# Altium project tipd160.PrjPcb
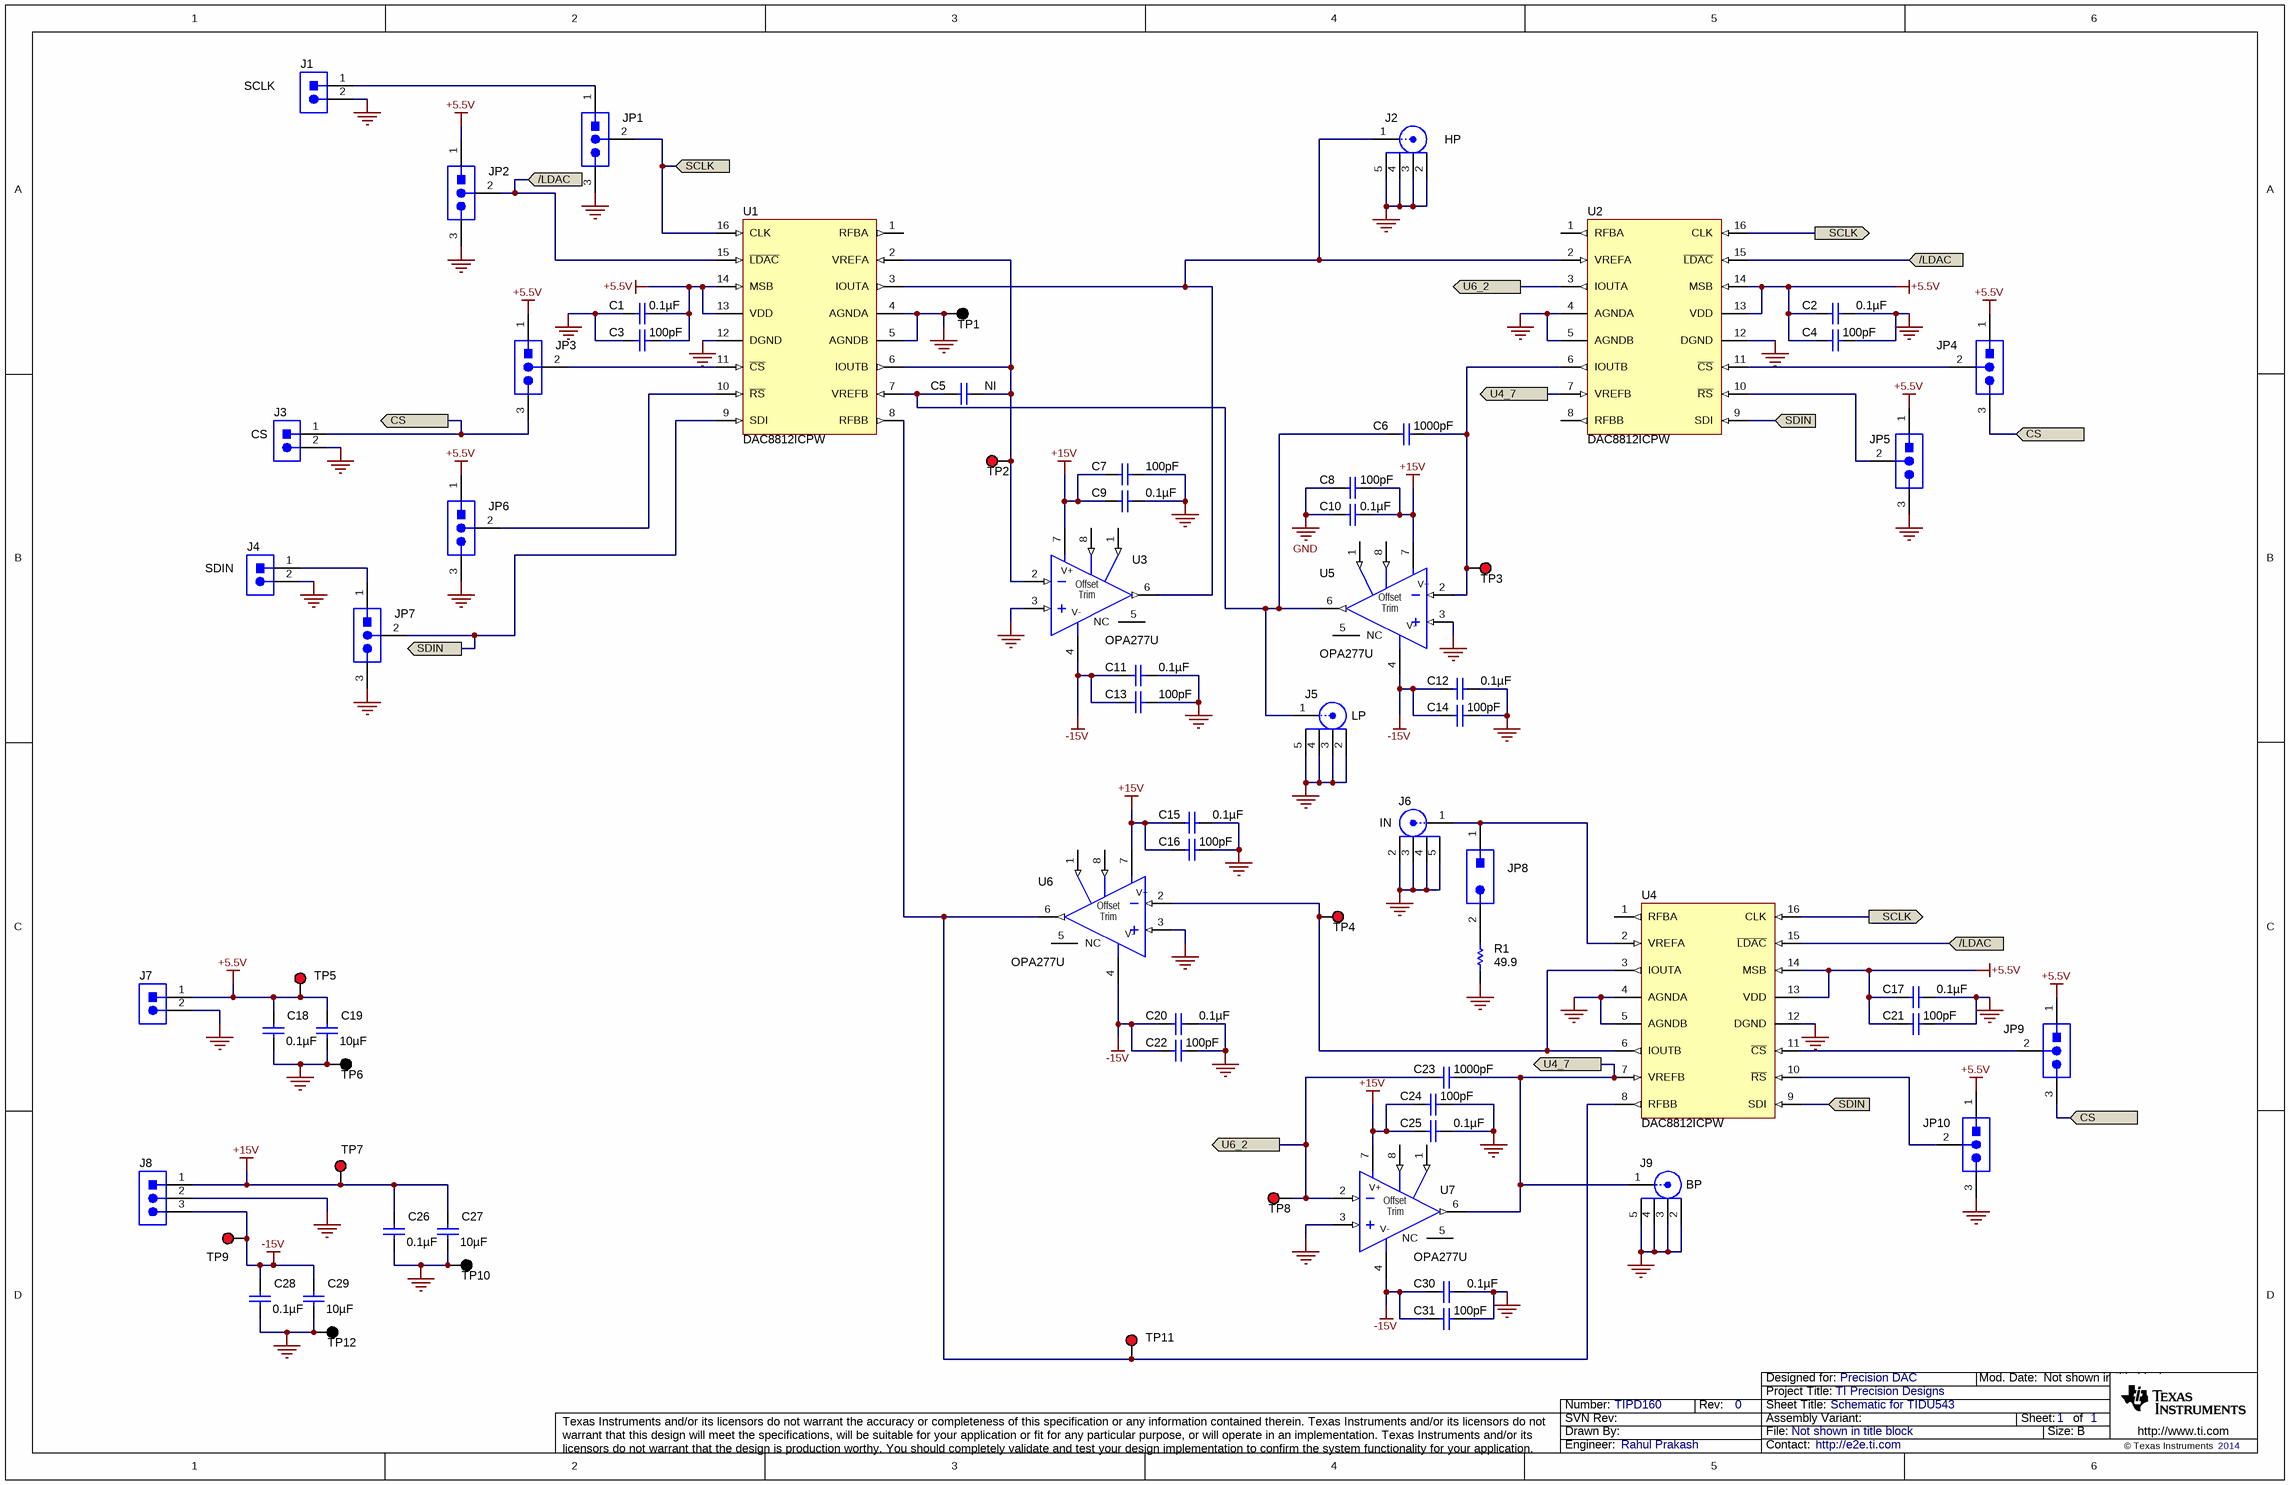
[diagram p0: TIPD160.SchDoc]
TechSupport: http://e2e.ti.com; SCH_Rev: 0; PRJ_Title: TI Precision Designs; PRJ_Number: TIPD160; PRJ_Engineer: Rahul Prakash; PRJ_Customer: Precision DAC; PCB_Rev: 1; PCB_Layout: Lisa Parker; CopyrightYear: 2014
1 sheet, 70 parts. Net scope: flat (ports and power ports of the same name join across sheets).
Board file: tipd160.PcbDoc

## Sheet TIPD160.SchDoc: Schematic for TIDU543
size 431 x 279 mm; Date: Not shown in title block; ApprovedBy: Not shown in title block; CheckedBy: Not shown in title block; Author: Not shown in title block; CompanyName: Not shown in title block; Engineer: Not shown in title block; Organization: Not shown in title block; Address1: Not shown in title block; Address2: Not shown in title block; Address3: Not shown in title block; Address4: Not shown in title block; DocumentNumber: 1; Revision: Use project parameter SCH_Rev; SheetNumber: 1; SheetTotal: 1; PageSetup: Record=PageOptions|CenterHorizontal=True|CenterVertical=True|PrintScale=1.00|XCorrection=1.00|YCorrection=1.00|PrintKind=0|BorderSize=5000000|LeftOffset=0|BottomOffset=0|Orientation=2|PaperLength=1000|PaperWidth=1000|Scale=100|PaperSource=15|PrintQuality=600|MediaType=1|DitherType=10|PaperKind=Letter|PrintScaleMode=1

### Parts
C1  ValueDisplayed: 0.1µF  [0603L]  (hidden comment: GRM188R61E104KA01D)
C2  ValueDisplayed: 0.1µF  [0603L]  (hidden comment: GRM188R61E104KA01D)
C3  ValueDisplayed: 100pF  [0603L]  (hidden comment: C1608C0G1H101J)
C4  ValueDisplayed: 100pF  [0603L]  (hidden comment: C1608C0G1H101J)
C5  value NI  [0603L]
C6  ValueDisplayed: 1000pF  [0603L]  (hidden comment: GRM188R71H102KA01D)
C7  ValueDisplayed: 100pF  [0603L]  (hidden comment: C1608C0G1H101J)
C8  ValueDisplayed: 100pF  [0603L]  (hidden comment: C1608C0G1H101J)
C9  ValueDisplayed: 0.1µF  [0603L]  (hidden comment: GRM188R61E104KA01D)
C10  ValueDisplayed: 0.1µF  [0603L]  (hidden comment: GRM188R61E104KA01D)
C11  ValueDisplayed: 0.1µF  [0603L]  (hidden comment: GRM188R61E104KA01D)
C12  ValueDisplayed: 0.1µF  [0603L]  (hidden comment: GRM188R61E104KA01D)
C13  ValueDisplayed: 100pF  [0603L]  (hidden comment: C1608C0G1H101J)
C14  ValueDisplayed: 100pF  [0603L]  (hidden comment: C1608C0G1H101J)
C15  ValueDisplayed: 0.1µF  [0603L]  (hidden comment: GRM188R61E104KA01D)
C16  ValueDisplayed: 100pF  [0603L]  (hidden comment: C1608C0G1H101J)
C17  ValueDisplayed: 0.1µF  [0603L]  (hidden comment: GRM188R61E104KA01D)
C18  ValueDisplayed: 0.1µF  [0603L]  (hidden comment: GRM188R61E104KA01D)
C19  ValueDisplayed: 10µF  [1206L]  (hidden comment: GRM31CR61E106KA12L)
C20  ValueDisplayed: 0.1µF  [0603L]  (hidden comment: GRM188R61E104KA01D)
C21  ValueDisplayed: 100pF  [0603L]  (hidden comment: C1608C0G1H101J)
C22  ValueDisplayed: 100pF  [0603L]  (hidden comment: C1608C0G1H101J)
C23  ValueDisplayed: 1000pF  [0603L]  (hidden comment: GRM188R71H102KA01D)
C24  ValueDisplayed: 100pF  [0603L]  (hidden comment: C1608C0G1H101J)
C25  ValueDisplayed: 0.1µF  [0603L]  (hidden comment: GRM188R61E104KA01D)
C26  ValueDisplayed: 0.1µF  [0603L]  (hidden comment: GRM188R61E104KA01D)
C27  ValueDisplayed: 10µF  [1206L]  (hidden comment: GRM31CR61E106KA12L)
C28  ValueDisplayed: 0.1µF  [0603L]  (hidden comment: GRM188R61E104KA01D)
C29  ValueDisplayed: 10µF  [1206L]  (hidden comment: GRM31CR61E106KA12L)
C30  ValueDisplayed: 0.1µF  [0603L]  (hidden comment: GRM188R61E104KA01D)
C31  ValueDisplayed: 100pF  [0603L]  (hidden comment: C1608C0G1H101J)
J1  TSW-102-07-G-S  [TSW-102-07-G-S]  (value not drawn)
J2  142-0701-201  [Johnson_142-0701-20x]  (value not drawn)
J3  TSW-102-07-G-S  [TSW-102-07-G-S]  (value not drawn)
J4  TSW-102-07-G-S  [TSW-102-07-G-S]  (value not drawn)
J5  142-0701-201  [Johnson_142-0701-20x]  (value not drawn)
J6  142-0701-201  [Johnson_142-0701-20x]  (value not drawn)
J7  ED555/2DS  [TERM_BLK_ED555-2DS]  (value not drawn)
J8  ED555/3DS  [TERM_BLK_ED555-3DS]  (value not drawn)
J9  142-0701-201  [Johnson_142-0701-20x]  (value not drawn)
JP1  TSW-103-07-G-S  [TSW-103-07-G-S]  (value not drawn)
JP2  TSW-103-07-G-S  [TSW-103-07-G-S]  (value not drawn)
JP3  TSW-103-07-G-S  [TSW-103-07-G-S]  (value not drawn)
JP4  TSW-103-07-G-S  [TSW-103-07-G-S]  (value not drawn)
JP5  TSW-103-07-G-S  [TSW-103-07-G-S]  (value not drawn)
JP6  TSW-103-07-G-S  [TSW-103-07-G-S]  (value not drawn)
JP7  TSW-103-07-G-S  [TSW-103-07-G-S]  (value not drawn)
JP8  TSW-102-07-G-S  [TSW-102-07-G-S]  (value not drawn)
JP9  TSW-103-07-G-S  [TSW-103-07-G-S]  (value not drawn)
JP10  TSW-103-07-G-S  [TSW-103-07-G-S]  (value not drawn)
R1  value 49.9  [0603L]  (hidden comment: RC0603FR-0749R9L)
TP1  5001  [Keystone5001]  (value not drawn)
TP2  5000  [Keystone5000]  (value not drawn)
TP3  5000  [Keystone5000]  (value not drawn)
TP4  5000  [Keystone5000]  (value not drawn)
TP5  5000  [Keystone5000]  (value not drawn)
TP6  5001  [Keystone5001]  (value not drawn)
TP7  5000  [Keystone5000]  (value not drawn)
TP8  5000  [Keystone5000]  (value not drawn)
TP9  5000  [Keystone5000]  (value not drawn)
TP10  5001  [Keystone5001]  (value not drawn)
TP11  5000  [Keystone5000]  (value not drawn)
TP12  5001  [Keystone5001]  (value not drawn)
U1  DAC8812ICPW  [PW0016A_N]
U2  DAC8812ICPW  [PW0016A_N]
U3  OPA277U  [D0008A_N]
U4  DAC8812ICPW  [PW0016A_N]
U5  OPA277U  [D0008A_N]
U6  OPA277U  [D0008A_N]
U7  OPA277U  [D0008A_N]

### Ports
/LDAC, CS, SCLK, SDIN, U4_7, U6_2

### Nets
+5.5V: C1.1 C2.2 C3.1 C4.2 C17.2 C18.2 C19.2 C21.2 J7.1 JP2.1 JP3.1 JP4.1 JP5.1 JP6.1 JP9.1 JP10.1 TP5.1 U1.13(VDD) U1.14(MSB) U2.13(VDD) U2.14(MSB) U4.13(VDD) U4.14(MSB)
+15V: C7.2 C8.1 C9.2 C10.1 C15.2 C16.2 C24.2 C25.2 C26.2 C27.2 J8.1 TP7.1 U3.7(V+) U5.7(V+) U6.7(V+) U7.7(V+)
-15V: C11.2 C12.2 C13.2 C14.2 C20.2 C22.2 C28.1 C29.1 C30.2 C31.2 J8.3 TP9.1 U3.4(V-) U5.4(V-) U6.4(V-) U7.4(V-)
GND: C1.2 C2.1 C3.2 C4.1 C7.1 C8.2 C9.1 C10.2 C11.1 C12.1 C13.1 C14.1 C15.1 C16.1 C17.1 C18.1 C19.1 C20.1 C21.1 C22.1 C24.1 C25.1 C26.1 C27.1 C28.2 C29.2 C30.1 C31.1 J1.2 J2.2 J2.3 J2.4 J2.5 J3.2 J4.2 J5.2 J5.3 J5.4 J5.5 J6.2 J6.3 J6.4 J6.5 J7.2 J8.2 J9.2 J9.3 J9.4 J9.5 JP1.3 JP2.3 JP5.3 JP6.3 JP7.3 JP10.3 R1.1 TP1.1 TP6.1 TP10.1 TP12.1 U1.4(AGNDA) U1.5(AGNDB) U1.12(DGND) U2.4(AGNDA) U2.5(AGNDB) U2.12(DGND) U3.3(IN+) U4.4(AGNDA) U4.5(AGNDB) U4.12(DGND) U5.3(IN+) U6.3(IN+) U7.3(IN+)
/LDAC: JP2.2 U1.15(~{LDAC}) U2.15(~{LDAC}) U4.15(~{LDAC}) ; port /LDAC
CS: J3.1 JP3.3 JP4.3 JP9.3 ; port CS
SCLK: JP1.2 U1.16(CLK) U2.16(CLK) U4.16(CLK) ; port SCLK
SDIN: JP7.2 U1.9(SDI) U2.9(SDI) U4.9(SDI) ; port SDIN
U4_7: C23.1 J9.1 U2.7(VREFB) U4.7(VREFB) U7.6(OUT) ; port U4_7
U6_2: C23.2 TP8.1 U2.3(IOUTA) U7.2(IN-) ; port U6_2
NetC5_1: C5.1 TP2.1 U1.2(VREFA) U1.6(IOUTB) U3.2(IN-)
NetC5_2: C5.2 C6.2 J5.1 U1.7(VREFB) U5.6(OUT)
NetC6_1: C6.1 TP3.1 U2.6(IOUTB) U5.2(IN-)
NetJ1_1: J1.1 JP1.1
NetJ2_1: J2.1 U1.3(IOUTA) U2.2(VREFA) U3.6(OUT)
NetJ4_1: J4.1 JP7.1
NetJ6_1: J6.1 JP8.1 U4.2(VREFA)
NetJP3_2: JP3.2 U1.11(~{CS})
NetJP4_2: JP4.2 U2.11(~{CS})
NetJP5_2: JP5.2 U2.10(~{RS})
NetJP6_2: JP6.2 U1.10(~{RS})
NetJP8_2: JP8.2 R1.2
NetJP9_2: JP9.2 U4.11(~{CS})
NetJP10_2: JP10.2 U4.10(~{RS})
NetTP4_1: TP4.1 U4.3(IOUTA) U4.6(IOUTB) U6.2(IN-)
NetTP11_1: TP11.1 U1.8(RFBB) U4.8(RFBB) U6.6(OUT)

Not connected (* = marked no-connect by the designer): U1 1(RFBA); U2 1(RFBA) 8(RFBB); U3 1(Offset_Trim) 5(NC) 8(Offset_Trim); U4 1(RFBA); U5 1(Offset_Trim) 5(NC) 8(Offset_Trim); U6 1(Offset_Trim) 5(NC) 8(Offset_Trim); U7 1(Offset_Trim) 5(NC) 8(Offset_Trim)

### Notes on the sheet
- SCLK
- (near J2) HP
- (near J3) CS
- (near J4) SDIN
- (near J5) LP
- (near J6) IN
- (near J9) BP

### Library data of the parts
C1 C2 C9-C12 C15 C17 C18 C20 C25 C26 C28 C30 = GRM188R61E104KA01D: CAP, CERM, 0.1uF, 25V, +/-10%, X5R, 0603; Manufacturer: MuRata; Polarized: N; CompType: Capacitor; U/M: EA; Cap_F: 0.0000001; Tolerance_%: 10; Value1: Unknown; VDC_V: 25; TaMin_C: -55; TaMax_C: 85; Cap_Case: 0603
C3 C4 C7 C8 C13 C14 C16 C21 C22 C24 C31 = C1608C0G1H101J: CAP, CERM, 100pF, 50V, +/-5%, C0G/NP0, 0603; Manufacturer: TDK; Polarized: N; CompType: Capacitor; U/M: EA; Cap_F: 0.0000000001; Tolerance_%: 5; ESR_Ohm: 0.1679; Value1: 0.1679 ohm; VDC_V: 50; TaMin_C: -55; TaMax_C: 125; Cap_Case: 0603
C5 = GRM188R71H102KA01D: Not Installed; Manufacturer: MuRata; Polarized: N; CompType: Capacitor; U/M: EA; Cap_F: 0.000000001; Tolerance_%: 10; Value1: Unknown; VDC_V: 50; Value2: 50V; TaMin_C: -55; TaMax_C: 125; Cap_Case: 0603
C6 C23 = GRM188R71H102KA01D: CAP, CERM, 1000pF, 50V, +/-10%, X7R, 0603; Manufacturer: MuRata; Polarized: N; CompType: Capacitor; U/M: EA; Cap_F: 0.000000001; Tolerance_%: 10; Value1: Unknown; VDC_V: 50; TaMin_C: -55; TaMax_C: 125; Cap_Case: 0603
C19 C27 C29 = GRM31CR61E106KA12L: CAP, CERM, 10uF, 25V, +/-10%, X5R, 1206; Manufacturer: MuRata; Polarized: N; CompType: Capacitor; U/M: EA; Cap_F: 0.00001; Tolerance_%: 10; ESR_Ohm: 0.004; Value1: 0.004 ohm; VDC_V: 25; TaMin_C: -55; TaMax_C: 85; Cap_Case: 1206
J1 J3 J4 JP8 = TSW-102-07-G-S: Header, 100mil, 2x1, Gold, TH; Manufacturer: Samtec; SymbolCreator: a0412235; U/M: EA
J2 J5 J6 J9 = 142-0701-201: Connector, TH, SMA; Manufacturer: Emerson Network Power; SymbolCreator: X0208326; U/M: EA
J7 = ED555/2DS: Terminal Block, 6A, 3.5mm Pitch, 2-Pos, TH; Manufacturer: On-Shore Technology; SymbolCreator: a0412235; CompType: Connector; U/M: EA
J8 = ED555/3DS: Terminal Block, 6A, 3.5mm Pitch, 3-Pos, TH; Manufacturer: On-Shore Technology; SymbolCreator: a0799628; CompType: Connector; U/M: EA
JP1-JP7 JP9 JP10 = TSW-103-07-G-S: Header, TH, 100mil, 3x1, Gold plated, 230 mil above insulator; Manufacturer: Samtec; SymbolCreator: a0799628; U/M: EA
R1 = RC0603FR-0749R9L: RES, 49.9 ohm, 1%, 0.1W, 0603; Manufacturer: Yageo America; CompType: Resistor; Value_Code: 49R9; Tolerance_%: 1; Power_W: 0.1; VDC_V: 150; TempCo: 200 ppm/C; EIA_Code: E96; U/M: EA
TP1 TP6 TP10 TP12 = 5001: Test Point, Miniature, Black, TH; Manufacturer: Keystone; CompType: Test Point Loop; U/M: EA
TP2-TP5 TP7-TP9 TP11 = 5000: Test Point, Miniature, Red, TH; Manufacturer: Keystone; CompType: Test Point Loop; U/M: EA
U1 U2 U4 = DAC8812ICPW: Dual, Serial Input 16-Bit Multiplying Digital-to-Analog Converter, PW0016A; Alternate Manufacturer: None; Manufacturer: Texas Instruments; SymbolCreator: x0208325; CompType: IC; U/M: EA
U3 U5-U7 = OPA277U: High Precision OPERATIONAL AMPLIFIER, D0008A; Alternate Manufacturer: None; Manufacturer: Texas Instruments; SymbolCreator: a0411947; CompType: IC; U/M: EA

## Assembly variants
001: not fitted FID1 FID2 FID3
